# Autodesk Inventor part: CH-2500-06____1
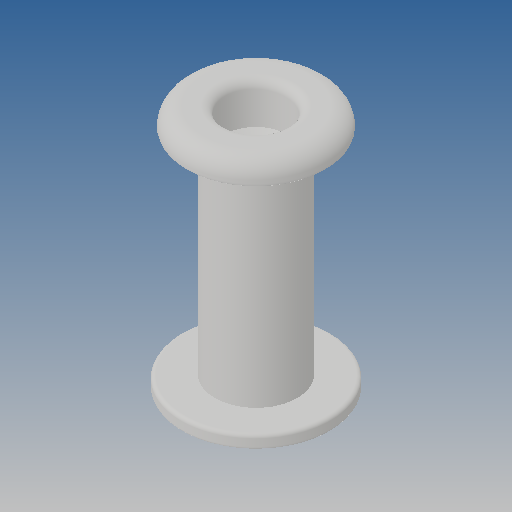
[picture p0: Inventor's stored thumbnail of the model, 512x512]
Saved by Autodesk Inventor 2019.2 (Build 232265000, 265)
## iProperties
Created: 2012-09
Part Number: CH-2500-06____1
Material: Ogólny
Document SubType Name: Modeling
Designer: CADENGINEERING4
Density: 1 g/cm^3
Appearance: Domyślna
Author: CADENGINEERING4
Revision Number: ÈÎºÎ
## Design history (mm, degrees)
feature "NONE"
node "Bryła1"
